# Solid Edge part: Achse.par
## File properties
Title: Achse
Author: horst
Template: Normal.par
Last saved by: Horst
Revision: 7
Application: Solid Edge
Material: 1.4435
Document Number: 4 02 4711/0.003
Revision: 45
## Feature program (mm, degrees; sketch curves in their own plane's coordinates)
sketch for "unnamed Protrusion 1" plane through (0, 0, 0) normal (1, 0, 0) x-axis (0, 1, 0)
  line (-150, -50) -> (150, -50)
  line (150, -50) -> (150, 50)
  line (150, 50) -> (-150, 50)
  line (-150, 50) -> (-150, -50)
extrude "unnamed Protrusion 1" add finite 20 along +normal
sketch for "unnamed Protrusion 2" plane through (20, 0, 0) normal (1, 0, 0) x-axis (0, 1, 0)
  circle centre (0, 0) radius 30
extrude "unnamed Protrusion 2" add finite 200 along +normal
